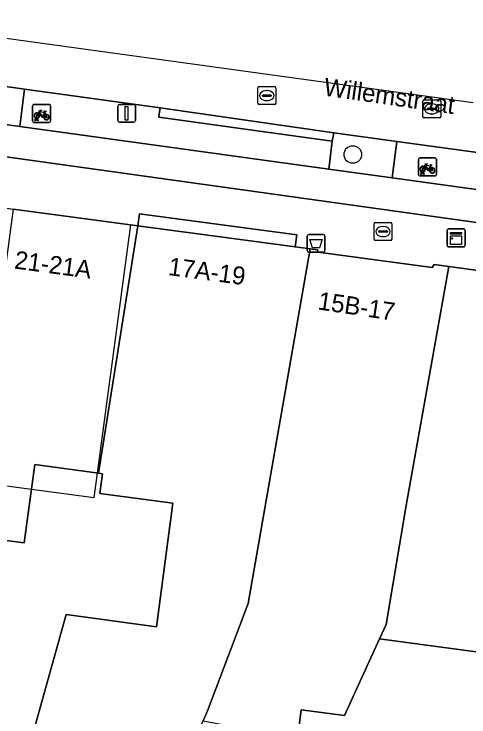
# Model space of a CAD drawing. Extents: x 160663 to 161506, y 382245 to 383291.
# Drawn here: x 161012.63 to 161038.03, y 383209.32 to 383248.56 of the extents above; entities that cross this region are included whole.
import ezdxf

# ---------------------------------------------------------------- set-up
doc = ezdxf.new("R2010")
doc.units = 0
for name, color, linetype in [('IMGEO_Afvalbak', 7, 'Continuous'), ('IMGEO_Berm_open', 7, 'Continuous'), ('IMGEO_Boom', 7, 'Continuous'), ('IMGEO_Brandkraan', 7, 'Continuous'), ('IMGEO_Erf', 7, 'Continuous'), ('IMGEO_Fietsenrek', 7, 'Continuous'), ('IMGEO_Fietspad_gesloten', 7, 'Continuous'), ('IMGEO_Groenvoorziening', 7, 'Continuous'), ('IMGEO_Kast', 7, 'Continuous'), ('IMGEO_Lichtmast', 7, 'Continuous'), ('IMGEO_Openbare_ruimte_label', 7, 'Continuous'), ('IMGEO_Pand', 7, 'Continuous'), ('IMGEO_Pand_nummerreeks', 7, 'Continuous'), ('IMGEO_Pand_vergunning_verleend', 7, 'Continuous'), ('IMGEO_Rijbaan_lokaal_gesloten', 7, 'Continuous'), ('IMGEO_Rioolput', 7, 'Continuous'), ('IMGEO_Voetpad_open', 7, 'Continuous')]:
    doc.layers.add(name, color=color, linetype=linetype)

msp = doc.modelspace()

# ---------------------------------------------------------------- linework, layer by layer
at = {"layer": 'IMGEO_Afvalbak'}
for p, q in [((161029.098, 383236.262), (161029.888, 383236.262)), ((161029.888, 383236.262), (161029.098, 383236.262)), ((161028.998, 383235.362), (161028.998, 383236.162)), ((161028.998, 383236.162), (161028.998, 383235.362)), ((161029.988, 383236.162), (161029.988, 383235.362)), ((161029.988, 383235.362), (161029.988, 383236.162)), ((161029.888, 383235.262), (161029.098, 383235.262)), ((161029.098, 383235.262), (161029.888, 383235.262))]:
    msp.add_line(p, q, dxfattribs=at)
msp.add_lwpolyline([(161029.141, 383235.976), (161029.845, 383235.976), (161029.696, 383235.506), (161029.29, 383235.506), (161029.141, 383235.976)], dxfattribs=at)
for centre, start, end in [((161029.098, 383236.162), 90, 180), ((161029.098, 383236.162), 90, 180), ((161029.888, 383236.162), 0, 90), ((161029.888, 383236.162), 360, 90), ((161029.098, 383235.362), 180, 270), ((161029.098, 383235.362), 180, 270), ((161029.888, 383235.362), 270, 0), ((161029.888, 383235.362), 270, 0)]:
    msp.add_arc(centre, 0.1, start, end, dxfattribs=at)
at = {"layer": 'IMGEO_Berm_open'}
for points in [[(161020.715, 383242.794), (161020.725, 383242.862), (161020.794, 383243.317), (161013.209, 383244.37), (161012.954, 383242.288), (161030.202, 383239.907), (161030.398, 383241.459), (161026.751, 383241.962)], [(161038.853, 383240.272), (161038.92, 383240.782), (161034.004, 383241.447), (161033.753, 383239.417), (161048.826, 383237.337), (161049.023, 383238.842), (161044.543, 383239.441)]]:
    msp.add_lwpolyline(points, close=True, dxfattribs=at)
at = {"layer": 'IMGEO_Boom'}
msp.add_circle((161031.545, 383240.719), 0.489, dxfattribs=at)
at = {"layer": 'IMGEO_Brandkraan'}
for p, q in [((161032.733, 383235.991), (161032.733, 383236.843)), ((161032.808, 383236.917), (161033.66, 383236.917)), ((161033.221, 383236.697), (161033.246, 383236.697)), ((161033.734, 383236.843), (161033.734, 383235.991)), ((161032.992, 383236.411), (161032.992, 383236.423)), ((161033.43, 383236.374), (161033.032, 383236.374)), ((161033.035, 383236.46), (161033.433, 383236.46)), ((161033.476, 383236.423), (161033.476, 383236.411)), ((161033.66, 383235.917), (161032.808, 383235.917)), ((161033.244, 383236.137), (161033.219, 383236.137))]:
    msp.add_line(p, q, dxfattribs=at)
for points in [[(161032.733, 383235.991), (161032.733, 383236.843)], [(161032.808, 383236.917), (161033.66, 383236.917)], [(161033.734, 383236.843), (161033.734, 383235.991)], [(161033.66, 383235.917), (161032.808, 383235.917)]]:
    msp.add_lwpolyline(points, dxfattribs=at)
for centre, radius, start, end in [((161032.81, 383236.841), 0.0765, 91.552, 178.448), ((161032.81, 383236.841), 0.0765, 91.552, 178.448), ((161033.658, 383236.841), 0.0765, 1.552, 88.448), ((161033.658, 383236.841), 0.0765, 1.552, 88.448), ((161033.032, 383236.42), 0.0403, 85.8775, 175.7526), ((161033.029, 383236.41), 0.0366, 178.938, 274.7102), ((161033.433, 383236.417), 0.043, 264.8664, 352.4533), ((161033.437, 383236.422), 0.0386, 1.7309, 96.639), ((161032.81, 383235.993), 0.0765, 181.552, 268.448), ((161032.81, 383235.993), 0.0765, 181.552, 268.448), ((161033.658, 383235.993), 0.0765, 271.552, 358.448), ((161033.658, 383235.993), 0.0765, 271.552, 358.448)]:
    msp.add_arc(centre, radius, start, end, dxfattribs=at)
for centre, major_axis, ratio, start_param, end_param in [((161033.22, 383236.417), (-0.387, 0.002), 0.722429, 4.712389, 7.853982), ((161033.245, 383236.417), (-0.39, 0.002), 0.717154, 1.570796, 4.712389)]:
    msp.add_ellipse(centre, major_axis=major_axis, ratio=ratio, start_param=start_param, end_param=end_param, dxfattribs=at)
at = {"layer": 'IMGEO_Erf'}
for points in [[(161013.753, 383208.642), (161015.536, 383215.037), (161020.579, 383214.359), (161021.506, 383221.255), (161017.421, 383221.804), (161017.568, 383222.896), (161017.343, 383222.926), (161013.786, 383223.405), (161013.198, 383219.032), (161010.588, 383219.382), (161010.207, 383219.433), (161010.049, 383219.455), (161007.135, 383208.859)], [(161045.079, 383212.056), (161033.038, 383213.675), (161031.092, 383209.397), (161028.668, 383209.722), (161028.452, 383208.117)]]:
    msp.add_lwpolyline(points, dxfattribs=at)
at = {"layer": 'IMGEO_Fietsenrek'}
for p, q in [((161013.669, 383242.584), (161013.669, 383243.425)), ((161013.669, 383243.425), (161013.669, 383242.584)), ((161013.744, 383243.509), (161014.585, 383243.509)), ((161014.585, 383243.509), (161013.744, 383243.509)), ((161014.669, 383243.434), (161014.669, 383242.593)), ((161014.669, 383242.593), (161014.669, 383243.434)), ((161014.356, 383243.058), (161014.392, 383242.963)), ((161014.594, 383242.509), (161013.753, 383242.509)), ((161013.753, 383242.509), (161014.594, 383242.509)), ((161013.796, 383242.593), (161013.835, 383242.753)), ((161013.83, 383242.593), (161013.796, 383242.593)), ((161013.865, 383242.741), (161013.83, 383242.593)), ((161013.907, 383242.765), (161013.906, 383242.769)), ((161013.948, 383242.593), (161013.914, 383242.735)), ((161013.938, 383242.776), (161013.939, 383242.769)), ((161013.946, 383242.739), (161013.981, 383242.593)), ((161013.981, 383242.593), (161013.948, 383242.593)), ((161035.291, 383240.524), (161036.132, 383240.524)), ((161036.132, 383240.524), (161035.291, 383240.524)), ((161035.216, 383239.599), (161035.216, 383240.44)), ((161035.216, 383240.44), (161035.216, 383239.599)), ((161036.216, 383240.449), (161036.216, 383239.608)), ((161036.216, 383239.608), (161036.216, 383240.449)), ((161035.343, 383239.608), (161035.382, 383239.768)), ((161035.412, 383239.756), (161035.377, 383239.608)), ((161035.454, 383239.78), (161035.453, 383239.784)), ((161035.495, 383239.608), (161035.461, 383239.75)), ((161035.485, 383239.791), (161035.486, 383239.784)), ((161035.493, 383239.754), (161035.528, 383239.608)), ((161035.903, 383240.073), (161035.939, 383239.978)), ((161036.141, 383239.524), (161035.3, 383239.524)), ((161035.3, 383239.524), (161036.141, 383239.524)), ((161035.377, 383239.608), (161035.343, 383239.608)), ((161035.528, 383239.608), (161035.495, 383239.608))]:
    msp.add_line(p, q, dxfattribs=at)
for points in [[(161014.003, 383242.983), (161013.951, 383242.893), (161013.911, 383242.868), (161013.912, 383242.915), (161013.967, 383243.009)], [(161013.982, 383243.035), (161014.077, 383243.199), (161014.163, 383243.185), (161014.165, 383243.176), (161014.109, 383243.165), (161014.082, 383243.12), (161014.338, 383243.079)], [(161014.278, 383242.791), (161014.228, 383242.791), (161014.037, 383243.042), (161014.018, 383243.01)], [(161014.325, 383243.054), (161014.068, 383243.095), (161014.051, 383243.066), (161014.218, 383242.846), (161014.325, 383243.054)], [(161014.373, 383242.956), (161014.343, 383243.033), (161014.234, 383242.815), (161014.277, 383242.815)], [(161014.307, 383242.815), (161014.427, 383242.814), (161014.383, 383242.928)], [(161014.403, 383242.935), (161014.458, 383242.79), (161014.308, 383242.79)], [(161014.338, 383243.079), (161014.363, 383243.128), (161014.357, 383243.132), (161014.334, 383243.136), (161014.322, 383243.143), (161014.321, 383243.146), (161014.323, 383243.151), (161014.418, 383243.136), (161014.42, 383243.126), (161014.41, 383243.113), (161014.398, 383243.107), (161014.384, 383243.113), (161014.356, 383243.058)], [(161035.529, 383240.05), (161035.624, 383240.214), (161035.71, 383240.2), (161035.712, 383240.191), (161035.656, 383240.18), (161035.629, 383240.135), (161035.885, 383240.094)], [(161035.872, 383240.069), (161035.615, 383240.11), (161035.598, 383240.081), (161035.765, 383239.861), (161035.872, 383240.069)], [(161035.885, 383240.094), (161035.91, 383240.143), (161035.904, 383240.147), (161035.881, 383240.151), (161035.869, 383240.158), (161035.868, 383240.161), (161035.87, 383240.166), (161035.965, 383240.151), (161035.967, 383240.141), (161035.957, 383240.128), (161035.945, 383240.122), (161035.931, 383240.128), (161035.903, 383240.073)], [(161035.55, 383239.998), (161035.498, 383239.908), (161035.458, 383239.883), (161035.459, 383239.93), (161035.514, 383240.024)], [(161035.825, 383239.806), (161035.775, 383239.806), (161035.584, 383240.057), (161035.565, 383240.025)], [(161035.92, 383239.971), (161035.89, 383240.048), (161035.781, 383239.83), (161035.824, 383239.83)], [(161035.854, 383239.83), (161035.974, 383239.829), (161035.93, 383239.943)], [(161035.95, 383239.95), (161036.005, 383239.805), (161035.855, 383239.805)]]:
    msp.add_lwpolyline(points, dxfattribs=at)
for centre, radius, start, end in [((161013.747, 383243.431), 0.0779, 92.4484, 184.2845), ((161013.747, 383243.431), 0.0779, 92.4484, 184.2845), ((161014.591, 383243.431), 0.0779, 2.4484, 94.2845), ((161014.591, 383243.431), 0.0779, 2.4484, 94.2845), ((161013.909, 383242.894), 0.159, 62.6766, 242.1369), ((161013.909, 383242.894), 0.129, 63.3192, 238.903), ((161013.909, 383242.894), 0.129, 283.6043, 43.4302), ((161013.909, 383242.894), 0.159, 283.5766, 46.6042), ((161014.436, 383242.81), 0.159, 113.3408, 178.3217), ((161014.436, 383242.81), 0.159, 187.0065, 105.7708), ((161014.436, 383242.81), 0.129, 113.923, 177.9556), ((161014.436, 383242.81), 0.129, 188.6715, 104.5883), ((161013.747, 383242.587), 0.0779, 182.4484, 274.2845), ((161013.747, 383242.587), 0.0779, 182.4484, 274.2845), ((161013.889, 383242.765), 0.0499, 12.8025, 158.6934), ((161013.909, 383242.894), 0.159, 253.9967, 271.7867), ((161013.889, 383242.765), 0.0174, 12.8025, 163.4502), ((161013.909, 383242.894), 0.129, 253.415, 269.0204), ((161014.591, 383242.587), 0.0779, 272.4484, 4.2845), ((161014.591, 383242.587), 0.0779, 272.4484, 4.2845), ((161035.294, 383240.446), 0.0779, 92.4484, 184.2845), ((161035.294, 383240.446), 0.0779, 92.4484, 184.2845), ((161036.138, 383240.446), 0.0779, 2.4484, 94.2845), ((161036.138, 383240.446), 0.0779, 2.4484, 94.2845), ((161035.456, 383239.909), 0.159, 62.6766, 242.1369), ((161035.456, 383239.909), 0.129, 63.3192, 238.903), ((161035.436, 383239.78), 0.0499, 12.8025, 158.6934), ((161035.456, 383239.909), 0.159, 253.9967, 271.7867), ((161035.436, 383239.78), 0.0174, 12.8025, 163.4502), ((161035.456, 383239.909), 0.129, 253.415, 269.0204), ((161035.456, 383239.909), 0.129, 283.6043, 43.4302), ((161035.456, 383239.909), 0.159, 283.5766, 46.6042), ((161035.983, 383239.825), 0.159, 113.3408, 178.3217), ((161035.983, 383239.825), 0.159, 187.0065, 105.7708), ((161035.983, 383239.825), 0.129, 113.923, 177.9556), ((161035.983, 383239.825), 0.129, 188.6715, 104.5883), ((161035.294, 383239.602), 0.0779, 182.4484, 274.2845), ((161035.294, 383239.602), 0.0779, 182.4484, 274.2845), ((161036.138, 383239.602), 0.0779, 272.4484, 4.2845), ((161036.138, 383239.602), 0.0779, 272.4484, 4.2845)]:
    msp.add_arc(centre, radius, start, end, dxfattribs=at)
at = {"layer": 'IMGEO_Fietspad_gesloten'}
for points in [[(160749.571, 383275.838), (160772.375, 383273.271), (160826.897, 383266.189), (160865.807, 383260.226), (160871.952, 383259.299), (160876.01, 383258.649), (160907.21, 383254.866), (160915.937, 383253.784), (160972.356, 383246.078), (160977.609, 383245.36), (160998.315, 383242.532), (161054.596, 383234.67)], [(161048.826, 383237.337), (161033.753, 383239.417), (161030.202, 383239.907), (161012.954, 383242.288), (161007.978, 383242.975), (160991.087, 383245.306), (160987.927, 383245.742), (160977.584, 383247.17), (160972.582, 383247.922), (160970.219, 383248.244), (160948.513, 383251.198), (160944.615, 383251.729), (160929.927, 383253.728), (160926.09, 383254.25), (160916.951, 383255.494), (160906.447, 383256.836), (160882.483, 383259.669), (160873.765, 383260.871), (160866.022, 383262.062), (160855.96, 383263.61), (160850.573, 383264.439)]]:
    msp.add_lwpolyline(points, dxfattribs=at)
at = {"layer": 'IMGEO_Groenvoorziening'}
for points in [[(161013.209, 383244.37), (161008.184, 383245.068), (161007.978, 383242.975), (161012.954, 383242.288)], [(161034.004, 383241.447), (161030.482, 383241.923), (161030.398, 383241.459), (161030.202, 383239.907), (161033.753, 383239.417)]]:
    msp.add_lwpolyline(points, close=True, dxfattribs=at)
at = {"layer": 'IMGEO_Kast'}
for p, q in [((161036.888, 383236.566), (161037.729, 383236.566)), ((161037.729, 383236.566), (161036.888, 383236.566)), ((161036.813, 383235.641), (161036.813, 383236.482)), ((161036.813, 383236.482), (161036.813, 383235.641)), ((161037.813, 383236.491), (161037.813, 383235.65)), ((161037.813, 383235.65), (161037.813, 383236.491)), ((161037.738, 383235.566), (161036.897, 383235.566)), ((161036.897, 383235.566), (161037.738, 383235.566))]:
    msp.add_line(p, q, dxfattribs=at)
for points in [[(161037.008, 383236.356), (161037.608, 383236.356), (161037.608, 383236.271), (161037.008, 383236.271), (161037.008, 383236.356)], [(161037.008, 383236.181), (161037.608, 383236.181), (161037.608, 383235.692), (161037.008, 383235.692), (161037.008, 383236.181)]]:
    msp.add_lwpolyline(points, dxfattribs=at)
msp.add_circle((161037.092, 383236.03), 0.0377, dxfattribs=at)
for centre, start, end in [((161036.891, 383236.488), 92.4484, 184.2845), ((161036.891, 383236.488), 92.4484, 184.2845), ((161037.735, 383236.488), 2.4484, 94.2845), ((161037.735, 383236.488), 2.4484, 94.2845), ((161036.891, 383235.644), 182.4484, 274.2845), ((161036.891, 383235.644), 182.4484, 274.2845), ((161037.735, 383235.644), 272.4484, 4.2845), ((161037.735, 383235.644), 272.4484, 4.2845)]:
    msp.add_arc(centre, 0.0779, start, end, dxfattribs=at)
at = {"layer": 'IMGEO_Lichtmast'}
for p, q in [((161018.421, 383242.615), (161018.421, 383243.415)), ((161018.421, 383243.415), (161018.421, 383242.615)), ((161018.521, 383243.515), (161019.311, 383243.515)), ((161019.311, 383243.515), (161018.521, 383243.515)), ((161019.411, 383243.415), (161019.411, 383242.615)), ((161019.411, 383242.615), (161019.411, 383243.415)), ((161019.311, 383242.515), (161018.521, 383242.515)), ((161018.521, 383242.515), (161019.311, 383242.515))]:
    msp.add_line(p, q, dxfattribs=at)
msp.add_lwpolyline([(161018.841, 383243.39), (161018.991, 383243.39), (161018.991, 383242.64), (161018.841, 383242.64), (161018.841, 383243.39)], dxfattribs=at)
for centre, start, end in [((161018.521, 383243.415), 90, 180), ((161018.521, 383243.415), 90, 180), ((161019.311, 383243.415), 0, 90), ((161019.311, 383243.415), 360, 90), ((161018.521, 383242.615), 180, 270), ((161018.521, 383242.615), 180, 270), ((161019.311, 383242.615), 270, 0), ((161019.311, 383242.615), 270, 0)]:
    msp.add_arc(centre, 0.1, start, end, dxfattribs=at)
at = {"layer": 'IMGEO_Pand'}
for points in [[(161019.54, 383236.74), (161012.588, 383237.67), (161011.106, 383226.811), (161010.119, 383219.942), (161010.049, 383219.455), (161010.207, 383219.433), (161010.588, 383219.382), (161013.198, 383219.032), (161013.786, 383223.405), (161017.343, 383222.926)], [(161029.172, 383235.45), (161028.332, 383235.563), (161019.54, 383236.74), (161017.343, 383222.926), (161017.568, 383222.896), (161017.421, 383221.804), (161021.506, 383221.255), (161020.579, 383214.359), (161015.536, 383215.037), (161013.753, 383208.642), (161021.694, 383205.717), (161023.186, 383209.11), (161023.428, 383209.659), (161025.701, 383215.654)], [(161036.914, 383234.459), (161036.09, 383234.572), (161035.971, 383234.418), (161029.622, 383235.271), (161029.57, 383235.397), (161029.172, 383235.45), (161025.701, 383215.654), (161023.428, 383209.659), (161023.186, 383209.11), (161028.452, 383208.117), (161028.668, 383209.722), (161031.092, 383209.397), (161033.038, 383213.675), (161033.403, 383214.478), (161034.519, 383221.118)], [(161047.469, 383226.498), (161048.632, 383226.341), (161049.45, 383232.725), (161048.165, 383232.814), (161048.179, 383232.914), (161036.914, 383234.459), (161034.519, 383221.118), (161033.403, 383214.478), (161033.038, 383213.675), (161045.079, 383212.056), (161045.684, 383213.199), (161046.971, 383222.787)]]:
    msp.add_lwpolyline(points, close=True, dxfattribs=at)
at = {"layer": 'IMGEO_Pand_vergunning_verleend'}
msp.add_lwpolyline([(160997.115, 383206.28), (161001.369, 383239.171), (161019.133, 383236.794), (161017.087, 383221.549), (161006.072, 383223.027), (161003.485, 383203.75)], close=True, dxfattribs=at)
at = {"layer": 'IMGEO_Rijbaan_lokaal_gesloten'}
msp.add_lwpolyline([(161038.265, 383243.607), (160926.374, 383259.023), (160926.118, 383256.999), (160926.07, 383256.622), (160926.395, 383256.579), (160930.26, 383256.062), (160941.434, 383254.466), (160944.887, 383253.96), (160947.814, 383253.531), (160970.494, 383250.343), (160971.748, 383250.181), (160972.88, 383250.034), (160977.884, 383249.337), (160988.207, 383247.841), (160991.302, 383247.393), (160999.446, 383246.282), (161008.184, 383245.068), (161013.209, 383244.37), (161020.794, 383243.317), (161030.482, 383241.923), (161034.004, 383241.447), (161038.92, 383240.782)], dxfattribs=at)
at = {"layer": 'IMGEO_Rioolput'}
for p, q in [((161026.245, 383243.58), (161026.245, 383244.432)), ((161026.32, 383244.506), (161027.172, 383244.506)), ((161027.246, 383244.432), (161027.246, 383243.58)), ((161026.504, 383244), (161026.504, 383244.012)), ((161026.547, 383244.049), (161026.945, 383244.049)), ((161026.733, 383244.286), (161026.758, 383244.286)), ((161026.988, 383244.012), (161026.988, 383244)), ((161026.942, 383243.963), (161026.544, 383243.963)), ((161026.756, 383243.726), (161026.731, 383243.726)), ((161035.457, 383242.839), (161035.457, 383243.691)), ((161035.532, 383243.765), (161036.384, 383243.765)), ((161036.458, 383243.691), (161036.458, 383242.839)), ((161027.172, 383243.506), (161026.32, 383243.506)), ((161035.716, 383243.259), (161035.716, 383243.271)), ((161035.759, 383243.308), (161036.157, 383243.308)), ((161035.945, 383243.545), (161035.97, 383243.545)), ((161036.2, 383243.271), (161036.2, 383243.259)), ((161036.154, 383243.222), (161035.756, 383243.222)), ((161035.968, 383242.985), (161035.943, 383242.985)), ((161036.384, 383242.765), (161035.532, 383242.765))]:
    msp.add_line(p, q, dxfattribs=at)
for points in [[(161026.245, 383243.58), (161026.245, 383244.432)], [(161026.32, 383244.506), (161027.172, 383244.506)], [(161027.246, 383244.432), (161027.246, 383243.58)], [(161035.457, 383242.839), (161035.457, 383243.691)], [(161035.532, 383243.765), (161036.384, 383243.765)], [(161036.458, 383243.691), (161036.458, 383242.839)], [(161027.172, 383243.506), (161026.32, 383243.506)], [(161036.384, 383242.765), (161035.532, 383242.765)]]:
    msp.add_lwpolyline(points, dxfattribs=at)
for centre, radius, start, end in [((161026.322, 383244.43), 0.0765, 91.552, 178.448), ((161026.322, 383244.43), 0.0765, 91.552, 178.448), ((161027.17, 383244.43), 0.0765, 1.552, 88.448), ((161027.17, 383244.43), 0.0765, 1.552, 88.448), ((161026.544, 383244.009), 0.0403, 85.8775, 175.7526), ((161026.949, 383244.011), 0.0386, 1.7309, 96.639), ((161026.541, 383243.999), 0.0366, 178.938, 274.7102), ((161026.945, 383244.006), 0.043, 264.8664, 352.4533), ((161035.534, 383243.689), 0.0765, 91.552, 178.448), ((161035.534, 383243.689), 0.0765, 91.552, 178.448), ((161036.382, 383243.689), 0.0765, 1.552, 88.448), ((161036.382, 383243.689), 0.0765, 1.552, 88.448), ((161026.322, 383243.582), 0.0765, 181.552, 268.448), ((161026.322, 383243.582), 0.0765, 181.552, 268.448), ((161027.17, 383243.582), 0.0765, 271.552, 358.448), ((161027.17, 383243.582), 0.0765, 271.552, 358.448), ((161035.756, 383243.268), 0.0403, 85.8775, 175.7526), ((161035.753, 383243.258), 0.0366, 178.938, 274.7102), ((161036.157, 383243.265), 0.043, 264.8664, 352.4533), ((161036.161, 383243.27), 0.0386, 1.7309, 96.639), ((161035.534, 383242.841), 0.0765, 181.552, 268.448), ((161035.534, 383242.841), 0.0765, 181.552, 268.448), ((161036.382, 383242.841), 0.0765, 271.552, 358.448), ((161036.382, 383242.841), 0.0765, 271.552, 358.448)]:
    msp.add_arc(centre, radius, start, end, dxfattribs=at)
for centre, major_axis, ratio, start_param, end_param in [((161026.732, 383244.006), (-0.387, 0.002), 0.722429, 4.712389, 7.853982), ((161026.757, 383244.006), (-0.39, 0.002), 0.717154, 1.570796, 4.712389), ((161035.944, 383243.265), (-0.387, 0.002), 0.722429, 4.712389, 7.853982), ((161035.969, 383243.265), (-0.39, 0.002), 0.717154, 1.570796, 4.712389)]:
    msp.add_ellipse(centre, major_axis=major_axis, ratio=ratio, start_param=start_param, end_param=end_param, dxfattribs=at)
at = {"layer": 'IMGEO_Voetpad_open'}
for points in [[(161020.794, 383243.317), (161020.725, 383242.862), (161020.715, 383242.794), (161026.751, 383241.962), (161030.398, 383241.459), (161030.482, 383241.923)], [(161028.332, 383235.563), (161028.421, 383236.228), (161019.629, 383237.405), (161019.54, 383236.74)]]:
    msp.add_lwpolyline(points, close=True, dxfattribs=at)
for points in [[(161054.596, 383234.67), (160998.315, 383242.532)], [(160987.783, 383240.842), (160994.411, 383240.035), (161000, 383239.354), (161001.369, 383239.171), (161001.967, 383239.091), (161002.097, 383240.063), (161011.513, 383238.803), (161011.383, 383237.831), (161012.588, 383237.67), (161019.54, 383236.74), (161019.629, 383237.405), (161028.421, 383236.228), (161028.332, 383235.563), (161029.172, 383235.45), (161029.57, 383235.397), (161029.622, 383235.271), (161035.971, 383234.418), (161036.09, 383234.572), (161036.914, 383234.459), (161048.179, 383232.914)]]:
    msp.add_lwpolyline(points, dxfattribs=at)

# ---------------------------------------------------------------- texts
at = {"layer": 'IMGEO_Openbare_ruimte_label'}
msp.add_text('Willemstraat', height=1, rotation=351.8375, dxfattribs=at).set_placement((161029.878, 383244.016))
at = {"layer": 'IMGEO_Pand_nummerreeks'}
for s, rotation, p in [('21-21A', 352.3797, (161012.612, 383234.358)), ('17A-19', 352.3739, (161021.206, 383233.994)), ('15B-17', 351.4801, (161029.553, 383232.077))]:
    msp.add_text(s, height=1, rotation=rotation, dxfattribs=at).set_placement(p)

doc.saveas('drawing.dxf')
